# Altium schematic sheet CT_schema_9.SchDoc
size 281 x 153 mm
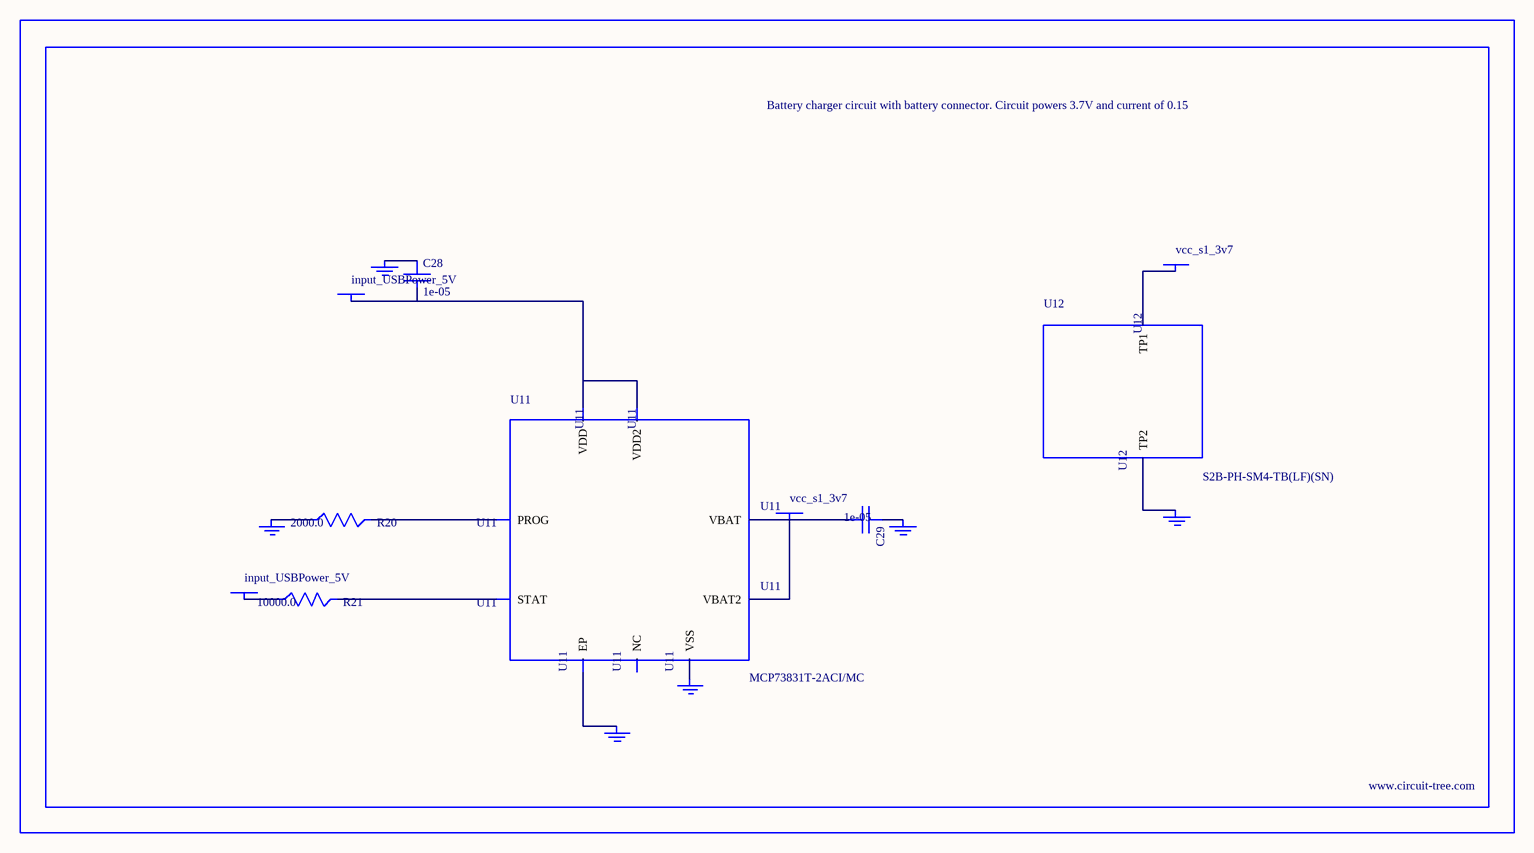
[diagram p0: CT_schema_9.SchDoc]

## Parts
BORDER8  (no value)
C28  1e-05  [C1206]
C29  1e-05  [C1206]
GND_INSTANCE_8_0  (no value)
GND_INSTANCE_8_1  (no value)
GND_INSTANCE_8_2  (no value)
GND_INSTANCE_8_3  (no value)
GND_INSTANCE_8_4  (no value)
GND_INSTANCE_8_5  (no value)
POWER_INSTANCE_8_0  input_USBPower_5V
POWER_INSTANCE_8_1  input_USBPower_5V
POWER_INSTANCE_8_2  vcc_s1_3v7
POWER_INSTANCE_8_3  vcc_s1_3v7
R20  2000.0  [R0603]
R21  10000.0  [R0603]
U11  MCP73831T-2ACI/MC  [DFN8_2X3MC]
U12  S2B-PH-SM4-TB(LF)(SN)  [JST-2-SMD]

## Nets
NetC28_1: C28.1 GND_INSTANCE_8_0.0(GND)
NetC28_2: C28.2 POWER_INSTANCE_8_0.0(PWR) U11.1(VDD) U11.2(VDD2)
NetC29_1: C29.1 GND_INSTANCE_8_1.0(GND)
NetC29_2: C29.2 POWER_INSTANCE_8_2.0(PWR) U11.3(VBAT) U11.4(VBAT2)
NetGND_INSTANCE_8_2_0: GND_INSTANCE_8_2.0(GND) R20.1
NetGND_INSTANCE_8_3_0: GND_INSTANCE_8_3.0(GND) U11.9(EP)
NetGND_INSTANCE_8_4_0: GND_INSTANCE_8_4.0(GND) U11.6(VSS)
NetGND_INSTANCE_8_5_0: GND_INSTANCE_8_5.0(GND) U12.2(TP2)
NetPOWER_INSTANCE_8_1_0: POWER_INSTANCE_8_1.0(PWR) R21.1
NetPOWER_INSTANCE_8_3_0: POWER_INSTANCE_8_3.0(PWR) U12.1(TP1)
NetR20_2: R20.2 U11.8(PROG)
NetR21_2: R21.2 U11.5(STAT)

Not connected (* = marked no-connect by the designer): U11 7(NC)

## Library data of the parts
BORDER8 = BORDER_PAGE8
C28 C29 = C1206C106K3RACTU
GND_INSTANCE_8_0-GND_INSTANCE_8_5 = GND
POWER_INSTANCE_8_0-POWER_INSTANCE_8_3 = PWR
R20 = RC0603JR-072KL
R21 = RC0603JR-0710KL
